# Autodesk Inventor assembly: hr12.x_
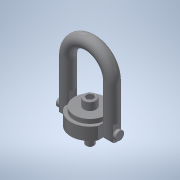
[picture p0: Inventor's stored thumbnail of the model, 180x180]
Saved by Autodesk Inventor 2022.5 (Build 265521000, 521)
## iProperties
Part Number: hr12.x_
Material: 一般
Document SubType Name: Assembly
Designer: ImaoCorp
Sending System: SOLIDWORKS 2017-2017317
MC: AMD64
MC_MODEL: Intel64 Family 6 Model 60 Stepping 3, GenuineIntel
OS: Windows_NT
FRU: Parasolid Version 29.0, build 201,  4-17-2017
FORMAT: text
GUISE: transmit
KEY: hr12
FILE: hr12.x_t
DATE: Mon Jul 01 17:37:14 2019
Author: ImaoCorp
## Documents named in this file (3)
- X:\14_SW2022-Inv2022\00_全2023-1023新製品(TCC)まで\h\hr12\HR12.iam
- X:\14_SW2022-Inv2022\00_全2023-1023新製品(TCC)まで\h\hr12\hr12_01.ipt
- X:\14_SW2022-Inv2022\00_全2023-1023新製品(TCC)まで\h\hr12\hr12_02.ipt
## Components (2 placed, 2 different names)
1. hr12_01
2. hr12_02
